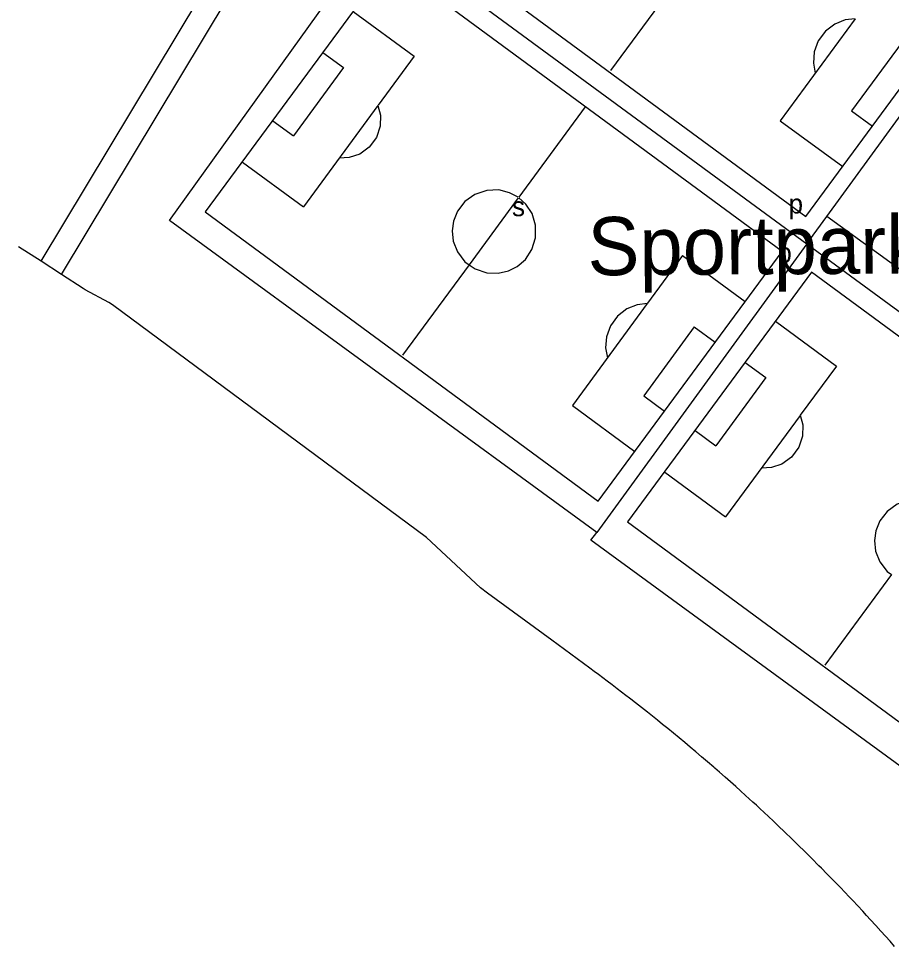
# Model space of a CAD drawing. Extents: x 155696 to 157795, y 382328 to 384028.
# Drawn here: x 156232.3 to 156412.1, y 382969.9 to 383161.2 of the extents above; entities that cross this region are included whole.
import ezdxf

# ---------------------------------------------------------------- set-up
doc = ezdxf.new("R2010")
doc.units = 0
for name, color, linetype in [('BLT_Basislijn', 7, 'Continuous'), ('BLT_Centroide', 7, 'Continuous'), ('BLT_Gemeentegrens', 7, 'Continuous'), ('BLT_Sport_parknaam', 7, 'Continuous')]:
    doc.layers.add(name, color=color, linetype=linetype)

msp = doc.modelspace()

# ---------------------------------------------------------------- linework, layer by layer
at = {"layer": 'BLT_Basislijn'}
for p, q in [((156236.89, 383111.16), (156285.18, 383191.45)), ((156241.1, 383108.46), (156289.58, 383189.06)), ((156306.4, 383179.59), (156394.72, 383114.76)), ((156398.84, 383120.42), (156437.42, 383173.47)), ((156367.93, 383169.17), (156354.22, 383150.48)), ((156301.22, 383162.67), (156313.78, 383153.45)), ((156404.63, 383161.13), (156389.21, 383140.13)), ((156414.33, 383156.36), (156403.91, 383142.15)), ((156294.99, 383154.18), (156299.21, 383151.08)), ((156313.78, 383153.45), (156306.34, 383143.33)), ((156299.21, 383151.08), (156288.9, 383137.04)), ((156306.28, 383143.24), (156290.95, 383122.36)), ((156348.99, 383142.98), (156335.33, 383124.38)), ((156403.91, 383142.15), (156408.21, 383139)), ((156284.67, 383140.14), (156288.9, 383137.04)), ((156389.21, 383140.13), (156402.09, 383130.67)), ((156278.39, 383131.58), (156290.95, 383122.36)), ((156335.22, 383124.23), (156325.11, 383110.46)), ((156394.72, 383114.76), (156398.84, 383120.42)), ((156448.24, 383084.39), (156398.84, 383120.42)), ((156394.72, 383114.76), (156351.43, 383055.23)), ((156394.72, 383114.76), (156443.98, 383078.61)), ((156369.1, 383112.35), (156361.87, 383102.51)), ((156369.1, 383112.35), (156381.98, 383102.9)), ((156325.11, 383110.46), (156311.39, 383091.78)), ((156361.81, 383102.43), (156346.39, 383081.42)), ((156371.51, 383097.65), (156361.08, 383083.45)), ((156371.51, 383097.65), (156375.81, 383094.5)), ((156388.24, 383098.79), (156400.8, 383089.57)), ((156382.01, 383090.3), (156386.23, 383087.2)), ((156400.8, 383089.57), (156393.36, 383079.44)), ((156386.23, 383087.2), (156375.92, 383073.15)), ((156361.08, 383083.45), (156365.38, 383080.29)), ((156346.39, 383081.42), (156359.27, 383071.97)), ((156393.3, 383079.36), (156377.97, 383058.48)), ((156371.69, 383076.25), (156375.92, 383073.15)), ((156365.41, 383067.7), (156377.97, 383058.48)), ((156412.14, 383046.58), (156398.42, 383027.9))]:
    msp.add_line(p, q, dxfattribs=at)
for points in [[(156313.53, 383180.03), (156394.51, 383120.41), (156432.43, 383171.91), (156351.45, 383231.53)], [(156270.71, 383121.33), (156351.69, 383061.7), (156389.61, 383113.21), (156308.63, 383172.83)], [(156357.73, 383057.45), (156438.71, 382997.82), (156476.63, 383049.33), (156395.65, 383108.95)]]:
    msp.add_lwpolyline(points, close=True, dxfattribs=at)
for points in [[(156351.43, 383055.23), (156263.35, 383119.54), (156306.4, 383179.59)], [(156404.66, 383161.17), (156402.58, 383160.91), (156400.45, 383160.06), (156398.52, 383158.58), (156397.05, 383156.58), (156396.22, 383154.3), (156396.05, 383152.01), (156396.42, 383149.94)], [(156306.31, 383143.29), (156306.83, 383141.31), (156306.79, 383139.03), (156306.02, 383136.7), (156304.53, 383134.68), (156302.55, 383133.25), (156300.38, 383132.53), (156298.34, 383132.43)], [(156335.19, 383124.36), (156333.46, 383125.3), (156331.22, 383125.86), (156328.73, 383125.78), (156326.29, 383124.95), (156324.22, 383123.45), (156322.73, 383121.52), (156321.9, 383119.45), (156321.63, 383117.45), (156321.85, 383115.31), (156322.71, 383113.09), (156324.25, 383111.08), (156325.11, 383110.46)], [(156325.11, 383110.46), (156326.35, 383109.58), (156328.75, 383108.78), (156331.12, 383108.69), (156333.22, 383109.17), (156335.02, 383110.08), (156336.71, 383111.54), (156338.06, 383113.57), (156338.8, 383116.02), (156338.79, 383118.6), (156338.07, 383120.98), (156336.81, 383122.91), (156335.35, 383124.25)], [(156361.84, 383102.47), (156359.76, 383102.21), (156357.63, 383101.36), (156355.7, 383099.88), (156354.23, 383097.88), (156353.4, 383095.59), (156353.22, 383093.31), (156353.6, 383091.24)], [(156393.34, 383079.41), (156393.85, 383077.42), (156393.81, 383075.14), (156393.04, 383072.82), (156391.56, 383070.8), (156389.57, 383069.37), (156387.41, 383068.65), (156385.36, 383068.54)], [(156422.21, 383060.48), (156420.48, 383061.42), (156418.24, 383061.98), (156415.76, 383061.9), (156413.31, 383061.07), (156411.24, 383059.57), (156409.76, 383057.64), (156408.92, 383055.57), (156408.65, 383053.57), (156408.87, 383051.43), (156409.73, 383049.21), (156411.27, 383047.2), (156412.14, 383046.58)], [(156440.34, 382987.8), (156439.42, 382988.47), (156350.17, 383053.65), (156351.43, 383055.23)]]:
    msp.add_lwpolyline(points, dxfattribs=at)
at = {"layer": 'BLT_Gemeentegrens'}
for points in [[(156236.89, 383111.16), (156232.25, 383114.14)], [(156241.1, 383108.46), (156236.89, 383111.16)], [(156412.8, 382969.93), (156411.84, 382971), (156410.92, 382972.04), (156409.98, 382973.08), (156408.91, 382974.26), (156407.83, 382975.44), (156407.03, 382976.31), (156406.23, 382977.17), (156405.19, 382978.28), (156404.15, 382979.39), (156403.38, 382980.2), (156402.61, 382981.02), (156401.54, 382982.14), (156400.46, 382983.25), (156398.84, 382984.92), (156397.73, 382986.05), (156397.2, 382986.57), (156395.74, 382988.04), (156394.28, 382989.49), (156392.93, 382990.82), (156391.59, 382992.13), (156390.2, 382993.46), (156388.82, 382994.79), (156387.8, 382995.75), (156386.78, 382996.71), (156385.89, 382997.55), (156384.99, 382998.38), (156384.3, 382999.02), (156383.6, 382999.66), (156382.82, 383000.37), (156382.05, 383001.07), (156381.05, 383001.97), (156380.06, 383002.87), (156378.96, 383003.84), (156377.86, 383004.81), (156376.69, 383005.84), (156375.71, 383006.7), (156375.52, 383006.86), (156374.26, 383007.95), (156373, 383009.04), (156371.85, 383010.02), (156370.69, 383010.99), (156369.53, 383011.97), (156368.36, 383012.94), (156367.21, 383013.89), (156366.06, 383014.83), (156364.99, 383015.7), (156363.91, 383016.57), (156362.9, 383017.38), (156361.89, 383018.19), (156360.66, 383019.16), (156359.42, 383020.13), (156358.43, 383020.9), (156358.16, 383021.11), (156357.43, 383021.67), (156356.54, 383022.36), (156355.64, 383023.05), (156354.59, 383023.85), (156353.54, 383024.64), (156352.65, 383025.3), (156351.76, 383025.97), (156350.89, 383026.61), (156350.01, 383027.26), (156342.14, 383033.04), (156328.92, 383042.75), (156327.46, 383043.82), (156316.34, 383054.19), (156251.59, 383102.15), (156250.89, 383102.67), (156246.01, 383105.3), (156245.59, 383105.57), (156241.1, 383108.46)]]:
    msp.add_lwpolyline(points, dxfattribs=at)

# ---------------------------------------------------------------- texts
at = {"layer": 'BLT_Centroide'}
for s, p in [('p', (156390.94, 383121.01)), ('s', (156333.95, 383120.45)), ('p', (156388.62, 383110.91))]:
    msp.add_text(s, height=4, dxfattribs=at).set_placement(p)
at = {"layer": 'BLT_Sport_parknaam'}
msp.add_text('Sportpark Meerhoven', height=12, rotation=0.3414, dxfattribs=at).set_placement((156349.53, 383108.26))

doc.saveas('drawing.dxf')
